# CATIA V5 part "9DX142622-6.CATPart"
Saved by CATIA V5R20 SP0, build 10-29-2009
Part number: 9DX142622-6
Revision: ANY
Definition: UNKNOWN
Nomenclature: 9DX142622-6
Source: Unknown
Bounding box of the stored display mesh (mm): x -15 to 15, y 0 to 20, z -15 to 15
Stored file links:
  C:\Users\Utente\Desktop\IO LAVORO\3D X SITO CF\CUMSA\3D files DX\DX 142622\9DX142622-6.CATPart
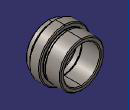
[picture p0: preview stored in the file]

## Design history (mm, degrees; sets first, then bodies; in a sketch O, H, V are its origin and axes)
Body1 "Redondeo3" (main body)
  Solid1: solid without history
